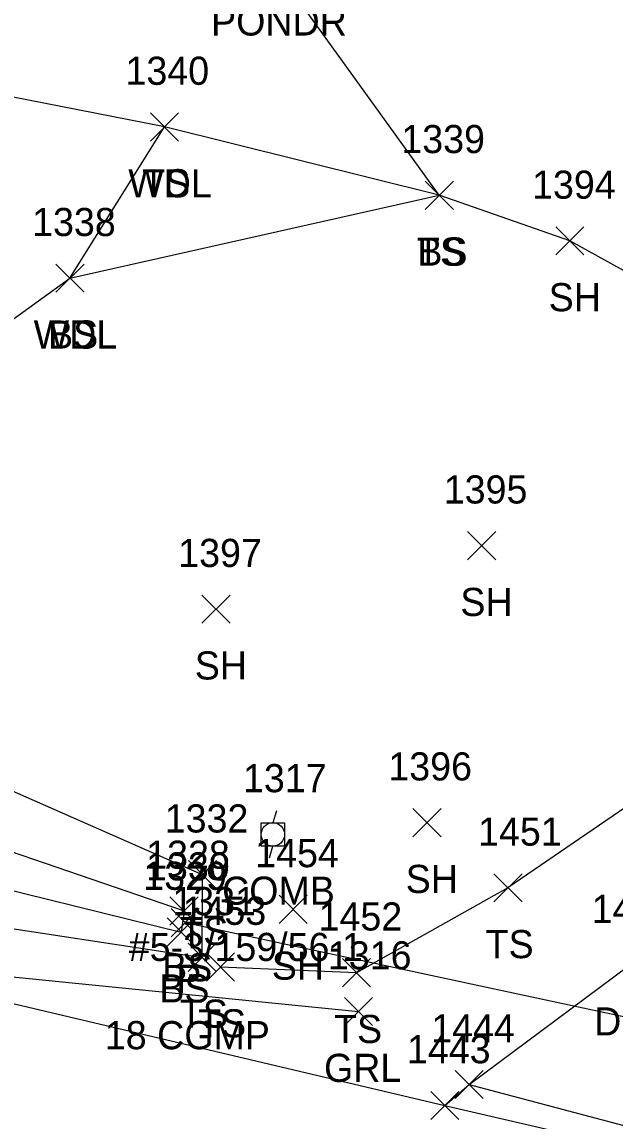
# Model space of a CAD drawing. Extents: x 1547013 to 1549434, y 267998 to 268739.
# Drawn here: x 1548625.3 to 1548667.4, y 268107.9 to 268186.1 of the extents above; entities that cross this region are included whole.
import ezdxf

# ---------------------------------------------------------------- set-up
doc = ezdxf.new("R2010")
doc.units = 0
for name, color, linetype in [('D_A', 7, 'Continuous'), ('D_C', 7, 'Continuous'), ('D_I', 7, 'Continuous'), ('D_TIC', 7, 'Continuous'), ('DCP', 7, 'Continuous'), ('L_A', 7, 'Continuous'), ('L_I', 7, 'Continuous'), ('L_TIC', 7, 'Continuous'), ('LAWA', 7, 'Continuous'), ('LELB', 7, 'Continuous'), ('LSOGP', 7, 'Continuous'), ('P_I', 7, 'Continuous'), ('P_TIC', 7, 'Continuous'), ('PET', 7, 'Continuous'), ('R_A', 7, 'Continuous'), ('R_I', 7, 'Continuous'), ('R_TIC', 7, 'Continuous'), ('RDG', 7, 'Continuous'), ('RDP', 7, 'Continuous'), ('RGR', 7, 'Continuous'), ('U_A', 7, 'Continuous'), ('U_C', 7, 'Continuous'), ('U_I', 7, 'Continuous'), ('UP', 7, 'Continuous')]:
    doc.layers.add(name, color=color, linetype=linetype)

msp = doc.modelspace()

# ---------------------------------------------------------------- linework, layer by layer
at = {"layer": 'D_TIC'}
for points in [[(1548635.864, 268121.044), (1548637.864, 268123.044)], [(1548637.864, 268121.044), (1548635.864, 268123.044)]]:
    msp.add_lwpolyline(points, dxfattribs=at)
at = {"layer": 'DCP'}
msp.add_lwpolyline([(1548636.864, 268122.044), (1548689.173, 268110.856)], dxfattribs=at)
at = {"layer": 'L_TIC'}
for points in [[(1548634.403, 268177.61), (1548636.403, 268179.61)], [(1548636.403, 268177.61), (1548634.403, 268179.61)], [(1548634.403, 268177.61), (1548636.403, 268179.61)], [(1548636.403, 268177.61), (1548634.403, 268179.61)], [(1548653.946, 268172.753), (1548655.946, 268174.753)], [(1548655.946, 268172.753), (1548653.946, 268174.753)], [(1548653.946, 268172.753), (1548655.946, 268174.753)], [(1548655.946, 268172.753), (1548653.946, 268174.753)], [(1548663.238, 268169.51), (1548665.238, 268171.51)], [(1548665.238, 268169.51), (1548663.238, 268171.51)], [(1548627.675, 268166.856), (1548629.675, 268168.856)], [(1548629.675, 268166.856), (1548627.675, 268168.856)], [(1548627.675, 268166.856), (1548629.675, 268168.856)], [(1548629.675, 268166.856), (1548627.675, 268168.856)], [(1548656.956, 268147.842), (1548658.956, 268149.842)], [(1548658.956, 268147.842), (1548656.956, 268149.842)], [(1548638.065, 268143.33), (1548640.065, 268145.33)], [(1548640.065, 268143.33), (1548638.065, 268145.33)], [(1548653.069, 268128.152), (1548655.069, 268130.152)], [(1548655.069, 268128.152), (1548653.069, 268130.152)], [(1548637.109, 268124.451), (1548639.109, 268126.451)], [(1548639.109, 268124.451), (1548637.109, 268126.451)], [(1548658.83, 268123.517), (1548660.83, 268125.517)], [(1548660.83, 268123.517), (1548658.83, 268125.517)], [(1548635.788, 268121.874), (1548637.788, 268123.874)], [(1548637.788, 268121.874), (1548635.788, 268123.874)], [(1548643.544, 268121.986), (1548645.544, 268123.986)], [(1548645.544, 268121.986), (1548643.544, 268123.986)], [(1548635.589, 268120.375), (1548637.589, 268122.375)], [(1548637.589, 268120.375), (1548635.589, 268122.375)], [(1548635.589, 268120.375), (1548637.589, 268122.375)], [(1548637.589, 268120.375), (1548635.589, 268122.375)], [(1548637.08, 268118.574), (1548639.08, 268120.574)], [(1548639.08, 268118.574), (1548637.08, 268120.574)], [(1548638.377, 268117.886), (1548640.377, 268119.886)], [(1548640.377, 268117.886), (1548638.377, 268119.886)], [(1548648.051, 268117.483), (1548650.051, 268119.483)], [(1548650.051, 268117.483), (1548648.051, 268119.483)]]:
    msp.add_lwpolyline(points, dxfattribs=at)
at = {"layer": 'LAWA'}
msp.add_lwpolyline([(1548603.989, 268158.225), (1548611.56, 268155.512), (1548628.675, 268167.856), (1548635.403, 268178.61), (1548610.953, 268183.401)], dxfattribs=at)
at = {"layer": 'LELB'}
for points in [[(1548654.946, 268173.753), (1548635.403, 268178.61)], [(1548628.675, 268167.856), (1548654.946, 268173.753)], [(1548567.105, 268144.51), (1548571.343, 268137.045), (1548586.37, 268132.193), (1548600.022, 268127.304), (1548618.136, 268122.596), (1548638.08, 268119.574), (1548638.109, 268125.451), (1548621.549, 268132.719), (1548599.121, 268139.132), (1548596.744, 268143.829), (1548611.56, 268155.512)], [(1548691.817, 268155.29), (1548674.281, 268134.397), (1548659.83, 268124.517), (1548649.051, 268118.483), (1548639.377, 268118.886)], [(1548593.686, 268141.194), (1548599.329, 268135.41), (1548620.257, 268128.544), (1548636.788, 268122.874), (1548636.589, 268121.375)], [(1548589.098, 268139.705), (1548597.809, 268132.823), (1548619.648, 268125.545), (1548636.589, 268121.375)]]:
    msp.add_lwpolyline(points, dxfattribs=at)
at = {"layer": 'LSOGP'}
msp.add_lwpolyline([(1548691.817, 268155.29), (1548664.238, 268170.51), (1548654.946, 268173.753), (1548643.145, 268190.113), (1548641.103, 268197.228), (1548631.959, 268206.471), (1548600.719, 268220.152), (1548585.674, 268217.811), (1548576.365, 268223.8), (1548554.199, 268208.91), (1548523.895, 268209.226), (1548498.289, 268206.717), (1548480.171, 268203.984), (1548463.541, 268201.585)], dxfattribs=at)
at = {"layer": 'P_TIC'}
for points in [[(1548654.338, 268108.044), (1548656.338, 268110.044)], [(1548656.338, 268108.044), (1548654.338, 268110.044)]]:
    msp.add_lwpolyline(points, dxfattribs=at)
at = {"layer": 'PET'}
msp.add_lwpolyline([(1548291.291, 268251.793), (1548331.751, 268232.06), (1548365.572, 268215.99), (1548397.036, 268199.918), (1548430.532, 268185.01), (1548469.559, 268167.88), (1548505.567, 268153.53), (1548548.446, 268139.726), (1548572.84, 268130.652), (1548596.653, 268123.565), (1548616.573, 268118.195), (1548655.338, 268109.044), (1548680.933, 268103.123), (1548700.801, 268099.763), (1548753.548, 268092.312), (1548788.113, 268088.532), (1548842.075, 268084.262), (1548868.979, 268083.237)], dxfattribs=at)
at = {"layer": 'R_TIC'}
for points in [[(1548648.201, 268114.719), (1548650.201, 268116.719)], [(1548650.201, 268114.719), (1548648.201, 268116.719)], [(1548656.065, 268109.53), (1548658.065, 268111.53)], [(1548658.065, 268109.53), (1548656.065, 268111.53)], [(1548656.065, 268109.53), (1548658.065, 268111.53)], [(1548658.065, 268109.53), (1548656.065, 268111.53)], [(1548654.338, 268108.044), (1548656.338, 268110.044)], [(1548656.338, 268108.044), (1548654.338, 268110.044)]]:
    msp.add_lwpolyline(points, dxfattribs=at)
at = {"layer": 'RDG'}
msp.add_lwpolyline([(1548657.065, 268110.53), (1548668.475, 268119.023), (1548685.95, 268139.594), (1548695.667, 268152.386)], dxfattribs=at)
at = {"layer": 'RDP'}
msp.add_lwpolyline([(1548655.338, 268109.044), (1548657.065, 268110.53), (1548678.169, 268104.932), (1548680.933, 268103.123)], dxfattribs=at)
at = {"layer": 'RGR'}
msp.add_lwpolyline([(1548553.774, 268143.213), (1548558.382, 268137.75), (1548564.172, 268134.614), (1548597.208, 268124.696), (1548620.291, 268118.608), (1548649.201, 268115.719)], dxfattribs=at)
at = {"layer": 'UP'}
for p, q in [((1548643.357, 268129.983), (1548643.107, 268129.15)), ((1548642.274, 268127.483), (1548642.274, 268129.15)), ((1548642.274, 268129.15), (1548643.941, 268129.15)), ((1548643.941, 268129.15), (1548643.941, 268127.483)), ((1548643.107, 268128.316), (1548643.107, 268128.316)), ((1548643.941, 268127.483), (1548642.274, 268127.483)), ((1548642.857, 268126.65), (1548643.107, 268127.483))]:
    msp.add_line(p, q, dxfattribs=at)
msp.add_circle((1548643.107, 268128.316), 0.833, dxfattribs=at)

# ---------------------------------------------------------------- texts
at = {"layer": 'D_A'}
msp.add_text('P', height=2, dxfattribs=at).set_placement((1548636.242, 268117.044))
at = {"layer": 'D_C'}
msp.add_text('18 CGMP', height=2, dxfattribs=at).set_placement((1548631.155, 268113.044))
at = {"layer": 'D_I'}
msp.add_text('1330', height=2, dxfattribs=at).set_placement((1548634.084, 268125.044))
at = {"layer": 'L_A'}
for s, p in [('PONDR', (1548638.712, 268185.113)), ('WDL', (1548632.82, 268173.61)), ('TS', (1548633.812, 268173.61)), ('TS', (1548653.355, 268168.753)), ('BS', (1548653.387, 268168.753)), ('SH', (1548662.726, 268165.51)), ('WDL', (1548626.092, 268162.856)), ('BS', (1548627.116, 268162.856)), ('SH', (1548656.444, 268143.842)), ('SH', (1548637.554, 268139.33)), ('SH', (1548652.557, 268124.152)), ('TS', (1548636.518, 268120.451)), ('TS', (1548658.24, 268119.517)), ('SH', (1548643.032, 268117.986)), ('BS', (1548635.229, 268117.874)), ('BS', (1548635.03, 268116.375)), ('BS', (1548635.03, 268116.375)), ('TS', (1548636.49, 268114.574)), ('TS', (1548637.787, 268113.886)), ('TS', (1548647.46, 268113.483))]:
    msp.add_text(s, height=2, dxfattribs=at).set_placement(p)
at = {"layer": 'L_I'}
for s, p in [('1340', (1548632.624, 268181.61)), ('1340', (1548632.624, 268181.61)), ('1339', (1548652.245, 268176.753)), ('1339', (1548652.245, 268176.753)), ('1394', (1548661.545, 268173.51)), ('1338', (1548625.982, 268170.856)), ('1338', (1548625.982, 268170.856)), ('1395', (1548655.264, 268151.842)), ('1397', (1548636.373, 268147.33)), ('1396', (1548651.321, 268132.152)), ('1332', (1548635.416, 268128.451)), ('1451', (1548657.704, 268127.517)), ('1328', (1548634.095, 268125.874)), ('1454', (1548641.851, 268125.986)), ('1329', (1548633.888, 268124.375)), ('1329', (1548633.888, 268124.375)), ('1331', (1548635.955, 268122.574)), ('1453', (1548636.684, 268121.886)), ('1452', (1548646.358, 268121.483))]:
    msp.add_text(s, height=2, dxfattribs=at).set_placement(p)
at = {"layer": 'P_I'}
msp.add_text('1443', height=2, dxfattribs=at).set_placement((1548652.645, 268112.044))
at = {"layer": 'R_A'}
for s, p in [('DRG', (1548665.963, 268114.023)), ('GRL', (1548646.744, 268110.719))]:
    msp.add_text(s, height=2, dxfattribs=at).set_placement(p)
at = {"layer": 'R_I'}
for s, p in [('1445', (1548665.783, 268122.023)), ('1316', (1548647.02, 268118.719)), ('1444', (1548654.372, 268113.53)), ('1444', (1548654.372, 268113.53)), ('1443', (1548652.645, 268112.044))]:
    msp.add_text(s, height=2, dxfattribs=at).set_placement(p)
at = {"layer": 'U_A'}
msp.add_text('COMB', height=2, dxfattribs=at).set_placement((1548639.493, 268123.316))
at = {"layer": 'U_C'}
msp.add_text('#5-3/159/56-1', height=2, dxfattribs=at).set_placement((1548632.856, 268119.316))
at = {"layer": 'U_I'}
msp.add_text('1317', height=2, dxfattribs=at).set_placement((1548640.982, 268131.316))

doc.saveas('drawing.dxf')
